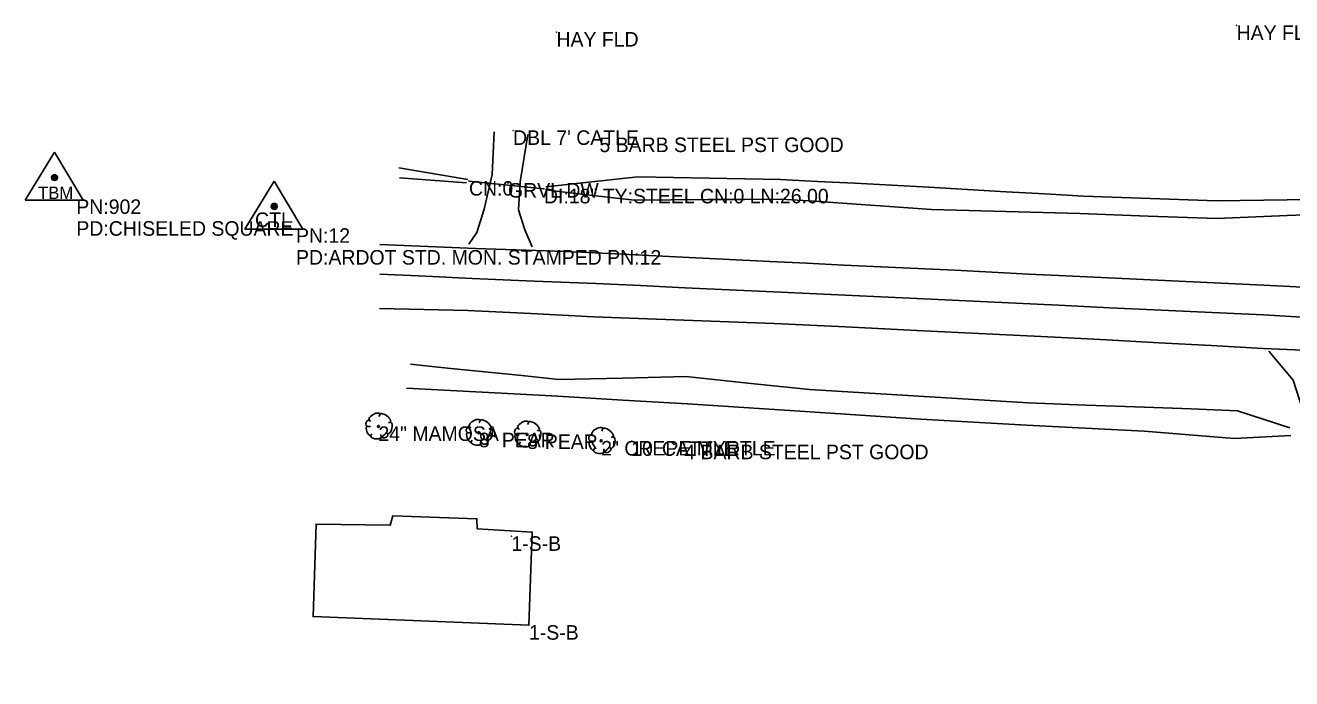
# Model space of a CAD drawing. Extents: x 1138803 to 1169983, y 1655906 to 1658226.
# Drawn here: x 1163774.6 to 1164210.1, y 1656653.9 to 1656878.5 of the extents above; entities that cross this region are included whole.
import ezdxf

# ---------------------------------------------------------------- set-up
doc = ezdxf.new("R2010")
doc.units = 0
for name, color, linetype in [('S_BUILDING', 7, 'Continuous'), ('S_BUILDING_ANNOT', 7, 'Continuous'), ('S_DITCHLINE', 7, 'Continuous'), ('S_DRG_PT_SYM', 7, 'Continuous'), ('S_DRIVEWAY', 7, 'Continuous'), ('S_EDGE_PAVEMENT', 7, 'Continuous'), ('S_GATE_ANNOT', 7, 'Continuous'), ('S_MSC_PT_SYM', 7, 'Continuous'), ('S_PAVEMENT_CROWN', 7, 'Continuous'), ('S_PRIMARY_CTL', 7, 'Continuous'), ('S_PRIMARY_CTL_ANNOT', 7, 'Continuous'), ('S_SIDE_DRAIN', 7, 'Continuous'), ('S_SIDE_DRAIN_ANNOT', 7, 'Continuous'), ('S_STR_PT_SYM', 7, 'Continuous'), ('S_SURVEY_TEXT_ANNOT', 7, 'Continuous'), ('S_TREE', 7, 'Continuous'), ('S_TREE_ANNOT', 7, 'Continuous')]:
    doc.layers.add(name, color=color, linetype=linetype)

msp = doc.modelspace()

# ---------------------------------------------------------------- linework, layer by layer
at = {"layer": 'S_BUILDING'}
for p, q in [((1163901, 1656709.89), (1163900.05, 1656706.68)), ((1163929.94, 1656708.84), (1163901, 1656709.89)), ((1163874.63, 1656707.06), (1163873.63, 1656675.29)), ((1163900.05, 1656706.68), (1163874.63, 1656707.06)), ((1163930, 1656705.43), (1163929.94, 1656708.84)), ((1163948.92, 1656704.23), (1163930, 1656705.43)), ((1163947.82, 1656672.32), (1163948.92, 1656704.23)), ((1163873.63, 1656675.29), (1163947.82, 1656672.32))]:
    msp.add_line(p, q, dxfattribs=at)
at = {"layer": 'S_DITCHLINE'}
for points in [[(1163926.76, 1656825.46), (1163903.1, 1656829.52)], [(1163926.31, 1656824.3), (1163903.28, 1656826.09)], [(1164232.81, 1656818.85), (1164208.55, 1656818.49), (1164184.28, 1656818.12), (1164161.4, 1656818.94), (1164138.52, 1656819.76), (1164125.22, 1656820.52), (1164111.91, 1656821.29), (1164098.61, 1656822.06), (1164085.31, 1656822.83), (1164072.56, 1656823.5), (1164059.81, 1656824.17), (1164047.07, 1656824.84), (1164034.32, 1656825.51), (1164009.8, 1656825.93), (1163985.29, 1656826.35), (1163969.44, 1656824.67), (1163953.6, 1656823)], [(1164232.68, 1656814.06), (1164208.48, 1656813.07), (1164184.28, 1656812.09), (1164160.76, 1656812.93), (1164137.24, 1656813.78), (1164124.5, 1656814.12), (1164111.76, 1656814.46), (1164099.01, 1656814.79), (1164086.27, 1656815.13), (1164073.34, 1656816.04), (1164060.41, 1656816.95), (1164047.48, 1656817.86), (1164034.55, 1656818.77), (1164021.94, 1656818.66), (1164009.34, 1656818.56), (1163996.73, 1656818.45), (1163984.12, 1656818.34), (1163968.78, 1656820.15), (1163953.44, 1656821.96)], [(1164209.43, 1656740.11), (1164191.44, 1656745.99), (1164175.44, 1656746.63), (1164159.44, 1656747.26), (1164139.45, 1656747.98), (1164119.46, 1656748.7), (1164100.65, 1656749.84), (1164081.85, 1656750.98), (1164063.07, 1656752.13), (1164044.3, 1656753.27), (1164023.08, 1656755.51), (1164001.87, 1656757.75), (1163979.98, 1656757.26), (1163958.08, 1656756.77), (1163945.34, 1656758.08), (1163932.6, 1656759.38), (1163919.85, 1656760.69), (1163907.11, 1656761.99)], [(1164209.79, 1656737.48), (1164190.35, 1656736.45), (1164174.81, 1656737.73), (1164159.28, 1656739), (1164139.07, 1656740.03), (1164118.87, 1656741.05), (1164100.68, 1656742.09), (1164082.5, 1656743.12), (1164063.47, 1656744.39), (1164044.44, 1656745.66), (1164023.36, 1656747), (1164002.28, 1656748.34), (1163980.03, 1656749.67), (1163957.78, 1656751), (1163944.75, 1656751.69), (1163931.73, 1656752.37), (1163918.7, 1656753.06), (1163905.68, 1656753.74)]]:
    msp.add_lwpolyline(points, dxfattribs=at)
at = {"layer": 'S_DRG_PT_SYM'}
for points in [[(1163927.18, 1656824.94), (1163927.18, 1656824.99), (1163927.18, 1656824.94), (1163927.13, 1656824.94), (1163927.18, 1656824.94), (1163927.18, 1656824.89), (1163927.18, 1656824.94), (1163927.23, 1656824.94)], [(1163952.97, 1656822.28), (1163952.97, 1656822.33), (1163952.97, 1656822.28), (1163952.92, 1656822.28), (1163952.97, 1656822.28), (1163952.97, 1656822.23), (1163952.97, 1656822.28), (1163953.02, 1656822.28)]]:
    msp.add_lwpolyline(points, dxfattribs=at)
at = {"layer": 'S_DRIVEWAY'}
for points in [[(1163935.86, 1656841.83), (1163935.18, 1656827.23), (1163932.45, 1656815.31), (1163929.91, 1656807.24), (1163927.13, 1656803.31)], [(1163948.96, 1656802.29), (1163946.41, 1656808.18), (1163944.24, 1656815.1), (1163944.84, 1656824.62), (1163947.41, 1656840.99)], [(1164230.04, 1656653.94), (1164227.96, 1656668.83), (1164225.87, 1656683.72), (1164222.6, 1656702.08), (1164219.44, 1656722.52), (1164217.3, 1656730.32), (1164214.92, 1656743.01), (1164210.53, 1656756.51), (1164202.18, 1656766.52)]]:
    msp.add_lwpolyline(points, dxfattribs=at)
at = {"layer": 'S_EDGE_PAVEMENT'}
for points in [[(1164225.06, 1656787.93), (1164200.44, 1656789.14), (1164183.43, 1656789.94), (1164166.41, 1656790.74), (1164149.39, 1656791.54), (1164132.38, 1656792.33), (1164119.65, 1656792.98), (1164106.93, 1656793.63), (1164094.21, 1656794.28), (1164081.48, 1656794.93), (1164068.77, 1656795.51), (1164056.07, 1656796.09), (1164043.36, 1656796.67), (1164030.65, 1656797.25), (1164014.48, 1656798.07), (1163998.31, 1656798.88), (1163982.13, 1656799.69), (1163965.96, 1656800.5), (1163953.72, 1656800.97), (1163929.5, 1656801.72), (1163913.02, 1656802.42), (1163896.55, 1656803.11)], [(1164224.92, 1656766.41), (1164200.22, 1656767.45), (1164182.32, 1656768.42), (1164164.42, 1656769.4), (1164146.53, 1656770.37), (1164128.63, 1656771.35), (1164104.88, 1656772.45), (1164081.13, 1656773.56), (1164056.61, 1656774.8), (1164032.08, 1656776.03), (1164016.55, 1656776.6), (1164001.03, 1656777.16), (1163985.5, 1656777.72), (1163969.97, 1656778.29), (1163948.4, 1656779.37), (1163926.83, 1656780.45), (1163911.61, 1656780.82), (1163896.38, 1656781.2)]]:
    msp.add_lwpolyline(points, dxfattribs=at)
at = {"layer": 'S_MSC_PT_SYM'}
for points in [[(1163957.26, 1656876.16), (1163957.26, 1656876.21), (1163957.26, 1656876.16), (1163957.21, 1656876.16), (1163957.26, 1656876.16), (1163957.26, 1656876.11), (1163957.26, 1656876.16), (1163957.31, 1656876.16)], [(1164191.12, 1656878.41), (1164191.12, 1656878.46), (1164191.12, 1656878.41), (1164191.07, 1656878.41), (1164191.12, 1656878.41), (1164191.12, 1656878.36), (1164191.12, 1656878.41), (1164191.17, 1656878.41)], [(1163942.35, 1656842.37), (1163942.35, 1656842.42), (1163942.35, 1656842.37), (1163942.3, 1656842.37), (1163942.35, 1656842.37), (1163942.35, 1656842.32), (1163942.35, 1656842.37), (1163942.4, 1656842.37)], [(1163972.04, 1656839.9), (1163972.04, 1656839.95), (1163972.04, 1656839.9), (1163971.99, 1656839.9), (1163972.04, 1656839.9), (1163972.04, 1656839.85), (1163972.04, 1656839.9), (1163972.09, 1656839.9)], [(1163940.6, 1656824.26), (1163940.6, 1656824.31), (1163940.6, 1656824.26), (1163940.55, 1656824.26), (1163940.6, 1656824.26), (1163940.6, 1656824.21), (1163940.6, 1656824.26), (1163940.65, 1656824.26)], [(1163982.97, 1656735.51), (1163982.97, 1656735.56), (1163982.97, 1656735.51), (1163982.92, 1656735.51), (1163982.97, 1656735.51), (1163982.97, 1656735.46), (1163982.97, 1656735.51), (1163983.02, 1656735.51)], [(1164001.23, 1656734.35), (1164001.23, 1656734.4), (1164001.23, 1656734.35), (1164001.18, 1656734.35), (1164001.23, 1656734.35), (1164001.23, 1656734.3), (1164001.23, 1656734.35), (1164001.28, 1656734.35)], [(1163941.77, 1656702.86), (1163941.77, 1656702.91), (1163941.77, 1656702.86), (1163941.72, 1656702.86), (1163941.77, 1656702.86), (1163941.77, 1656702.81), (1163941.77, 1656702.86), (1163941.82, 1656702.86)]]:
    msp.add_lwpolyline(points, dxfattribs=at)
at = {"layer": 'S_PAVEMENT_CROWN'}
msp.add_lwpolyline([(1164224.86, 1656777.51), (1164200.4, 1656778.96), (1164182.76, 1656779.78), (1164165.13, 1656780.6), (1164147.49, 1656781.42), (1164129.86, 1656782.24), (1164105.52, 1656783.4), (1164081.18, 1656784.57), (1164056.53, 1656785.7), (1164031.88, 1656786.84), (1164016.65, 1656787.56), (1164001.42, 1656788.28), (1163986.18, 1656789.01), (1163970.95, 1656789.73), (1163949.63, 1656790.57), (1163928.31, 1656791.41), (1163912.39, 1656792.2), (1163896.48, 1656792.98)], dxfattribs=at)
at = {"layer": 'S_PRIMARY_CTL'}
for p, q in [((1163784.67, 1656834.85), (1163774.64, 1656818.34)), ((1163784.67, 1656834.85), (1163794.5, 1656818.34)), ((1163860.21, 1656824.93), (1163850.17, 1656808.41)), ((1163860.21, 1656824.93), (1163870.03, 1656808.41)), ((1163774.64, 1656818.34), (1163794.5, 1656818.34)), ((1163850.17, 1656808.41), (1163870.03, 1656808.41))]:
    msp.add_line(p, q, dxfattribs=at)
for centre, radius in [((1163784.67, 1656826.15), 1.04), ((1163784.67, 1656826.15), 0.609), ((1163784.67, 1656826.15), 0.344), ((1163860.21, 1656816.23), 1.04), ((1163860.21, 1656816.23), 0.609), ((1163860.21, 1656816.23), 0.344)]:
    msp.add_circle(centre, radius, dxfattribs=at)
at = {"layer": 'S_SIDE_DRAIN'}
msp.add_line((1163952.97, 1656822.28), (1163927.18, 1656824.94), dxfattribs=at)
at = {"layer": 'S_STR_PT_SYM'}
for points in [[(1163901, 1656709.89), (1163901, 1656709.94), (1163901, 1656709.89), (1163900.95, 1656709.89), (1163901, 1656709.89), (1163901, 1656709.84), (1163901, 1656709.89), (1163901.05, 1656709.89)], [(1163874.63, 1656707.06), (1163874.63, 1656707.11), (1163874.63, 1656707.06), (1163874.58, 1656707.06), (1163874.63, 1656707.06), (1163874.63, 1656707.01), (1163874.63, 1656707.06), (1163874.68, 1656707.06)], [(1163900.05, 1656706.68), (1163900.05, 1656706.73), (1163900.05, 1656706.68), (1163900, 1656706.68), (1163900.05, 1656706.68), (1163900.05, 1656706.63), (1163900.05, 1656706.68), (1163900.1, 1656706.68)], [(1163929.94, 1656708.84), (1163929.94, 1656708.89), (1163929.94, 1656708.84), (1163929.89, 1656708.84), (1163929.94, 1656708.84), (1163929.94, 1656708.79), (1163929.94, 1656708.84), (1163929.99, 1656708.84)], [(1163930, 1656705.43), (1163930, 1656705.48), (1163930, 1656705.43), (1163929.95, 1656705.43), (1163930, 1656705.43), (1163930, 1656705.38), (1163930, 1656705.43), (1163930.05, 1656705.43)], [(1163948.92, 1656704.23), (1163948.92, 1656704.28), (1163948.92, 1656704.23), (1163948.87, 1656704.23), (1163948.92, 1656704.23), (1163948.92, 1656704.18), (1163948.92, 1656704.23), (1163948.97, 1656704.23)], [(1163873.63, 1656675.29), (1163873.63, 1656675.34), (1163873.63, 1656675.29), (1163873.58, 1656675.29), (1163873.63, 1656675.29), (1163873.63, 1656675.24), (1163873.63, 1656675.29), (1163873.68, 1656675.29)], [(1163947.82, 1656672.32), (1163947.82, 1656672.37), (1163947.82, 1656672.32), (1163947.77, 1656672.32), (1163947.82, 1656672.32), (1163947.82, 1656672.27), (1163947.82, 1656672.32), (1163947.87, 1656672.32)]]:
    msp.add_lwpolyline(points, dxfattribs=at)
at = {"layer": 'S_TREE'}
for p, q in [((1163896.6, 1656744.88), (1163896.22, 1656744.02)), ((1163892.15, 1656740.54), (1163893.27, 1656740.54)), ((1163892.81, 1656742.86), (1163893.31, 1656742.28)), ((1163900.17, 1656742.09), (1163899.51, 1656741.82)), ((1163927.29, 1656740.7), (1163927.79, 1656740.12)), ((1163931.09, 1656742.72), (1163930.7, 1656741.87)), ((1163947.73, 1656742.12), (1163947.34, 1656741.27)), ((1163893.31, 1656737.36), (1163893.78, 1656738.06)), ((1163896.99, 1656737.09), (1163896.91, 1656737.86)), ((1163899.39, 1656737.98), (1163898.93, 1656738.41)), ((1163926.63, 1656738.38), (1163927.75, 1656738.38)), ((1163927.79, 1656735.2), (1163928.26, 1656735.9)), ((1163933.88, 1656735.82), (1163933.41, 1656736.25)), ((1163934.65, 1656739.93), (1163933.99, 1656739.66)), ((1163943.27, 1656737.78), (1163944.39, 1656737.78)), ((1163943.93, 1656740.11), (1163944.43, 1656739.52)), ((1163951.29, 1656739.33), (1163950.63, 1656739.06)), ((1163969.4, 1656737.86), (1163969.91, 1656737.28)), ((1163973.2, 1656739.88), (1163972.81, 1656739.03)), ((1163976.77, 1656737.09), (1163976.11, 1656736.82)), ((1163931.47, 1656734.93), (1163931.4, 1656735.7)), ((1163944.43, 1656734.6), (1163944.9, 1656735.3)), ((1163948.11, 1656734.33), (1163948.04, 1656735.11)), ((1163950.52, 1656735.22), (1163950.05, 1656735.65)), ((1163968.75, 1656735.54), (1163969.87, 1656735.54)), ((1163969.91, 1656732.36), (1163970.37, 1656733.06)), ((1163973.59, 1656732.09), (1163973.51, 1656732.87)), ((1163975.99, 1656732.98), (1163975.53, 1656733.41))]:
    msp.add_line(p, q, dxfattribs=at)
for centre in [(1163896.05, 1656740.63), (1163930.53, 1656738.47), (1163947.17, 1656737.88), (1163972.64, 1656735.63)]:
    msp.add_circle(centre, 0.341, dxfattribs=at)
for centre, major_axis, ratio, start_param, end_param in [((1163894.71, 1656743.83), (1.86, 1.08), 0.471018, 0, 3.141593), ((1163898.37, 1656743.51), (-1.81, 1.36), 0.405113, 3.141593, 6.283186), ((1163892.48, 1656741.72), (0.31, 1.03), 0.646762, 0, 3.141593), ((1163892.78, 1656739.07), (-0.61, 1.6), 0.420543, 6.283185, 9.424777), ((1163899.72, 1656740.1), (0.46, 2.04), 0.482994, 3.141593, 6.283185), ((1163926.96, 1656739.56), (0.31, 1.03), 0.646762, 0, 3.141593), ((1163929.19, 1656741.67), (1.86, 1.08), 0.471018, 0, 3.141593), ((1163932.85, 1656741.35), (-1.81, 1.36), 0.405113, 3.141593, 6.283186), ((1163945.83, 1656741.08), (1.86, 1.08), 0.471018, 0, 3.141593), ((1163949.49, 1656740.75), (-1.81, 1.36), 0.405113, 3.141593, 6.283186), ((1163971.31, 1656738.84), (1.86, 1.08), 0.471018, 0, 3.141593), ((1163974.96, 1656738.51), (-1.81, 1.36), 0.405113, 3.141593, 6.283186), ((1163895.24, 1656737.29), (-1.83, 0.19), 0.529943, 0, 3.141593), ((1163898.2, 1656737.58), (1.09, 0.46), 0.711534, 3.141592, 6.283185), ((1163927.26, 1656736.91), (-0.61, 1.6), 0.420543, 6.283185, 9.424777), ((1163934.2, 1656737.94), (0.46, 2.04), 0.482994, 3.141593, 6.283185), ((1163943.6, 1656738.96), (0.31, 1.03), 0.646762, 0, 3.141593), ((1163943.9, 1656736.31), (-0.61, 1.6), 0.420543, 6.283185, 9.424777), ((1163950.84, 1656737.35), (0.46, 2.04), 0.482994, 3.141593, 6.283185), ((1163969.07, 1656736.72), (0.31, 1.03), 0.646762, 0, 3.141593), ((1163976.32, 1656735.1), (0.46, 2.04), 0.482994, 3.141593, 6.283185), ((1163929.72, 1656735.13), (-1.83, 0.19), 0.529943, 0, 3.141593), ((1163932.68, 1656735.42), (1.09, 0.46), 0.711534, 3.141592, 6.283185), ((1163946.36, 1656734.53), (-1.83, 0.19), 0.529943, 0, 3.141593), ((1163949.32, 1656734.82), (1.09, 0.46), 0.711534, 3.141592, 6.283185), ((1163969.38, 1656734.07), (-0.61, 1.6), 0.420543, 6.283185, 9.424777), ((1163971.84, 1656732.29), (-1.83, 0.19), 0.529943, 0, 3.141593), ((1163974.8, 1656732.58), (1.09, 0.46), 0.711534, 3.141592, 6.283185)]:
    msp.add_ellipse(centre, major_axis=major_axis, ratio=ratio, start_param=start_param, end_param=end_param, dxfattribs=at)

# ---------------------------------------------------------------- texts
at = {"layer": 'S_BUILDING_ANNOT'}
msp.add_text('1-S-B', height=5, dxfattribs=at).set_placement((1163947.82, 1656667.32))
at = {"layer": 'S_GATE_ANNOT'}
for s, p in [("DBL 7' CATLE", (1163942.35, 1656837.37)), ("10' CATTLE", (1163982.97, 1656730.51))]:
    msp.add_text(s, height=5, dxfattribs=at).set_placement(p)
at = {"layer": 'S_PRIMARY_CTL'}
for s, height, p in [('TBM', 4.287, (1163779.02, 1656818.76)), ('CTL', 5, (1163853.62, 1656809.15))]:
    msp.add_text(s, height=height, rotation=360, dxfattribs=at).set_placement(p)
at = {"layer": 'S_PRIMARY_CTL_ANNOT'}
for s, p in [('PN:902', (1163792.17, 1656813.65)), ('PD:CHISELED SQUARE', (1163792.17, 1656806.15)), ('PN:12', (1163867.71, 1656803.73)), ('PD:ARDOT STD. MON. STAMPED PN:12', (1163867.71, 1656796.23))]:
    msp.add_text(s, height=5, dxfattribs=at).set_placement(p)
at = {"layer": 'S_SIDE_DRAIN_ANNOT'}
for s, p in [('CN:0', (1163927.18, 1656819.94)), ('DI:18" TY:STEEL CN:0 LN:26.00', (1163952.97, 1656817.28))]:
    msp.add_text(s, height=5, dxfattribs=at).set_placement(p)
at = {"layer": 'S_SURVEY_TEXT_ANNOT'}
for s, p in [('HAY FLD', (1163957.26, 1656871.16)), ('HAY FLD', (1164191.12, 1656873.41)), ('5 BARB STEEL PST GOOD', (1163972.04, 1656834.9)), ('GRVL DW', (1163940.6, 1656819.26)), ('4 BARB STEEL PST GOOD', (1164001.23, 1656729.35)), ('1-S-B', (1163941.77, 1656697.86))]:
    msp.add_text(s, height=5, dxfattribs=at).set_placement(p)
at = {"layer": 'S_TREE_ANNOT'}
for s, p in [('24" MAMOSA', (1163896.05, 1656735.63)), ('8" PEAR', (1163930.53, 1656733.47)), ('8"PEAR', (1163947.17, 1656732.88)), ('2" CREPE MYRTLE', (1163972.64, 1656730.63))]:
    msp.add_text(s, height=5, dxfattribs=at).set_placement(p)

doc.saveas('drawing.dxf')
